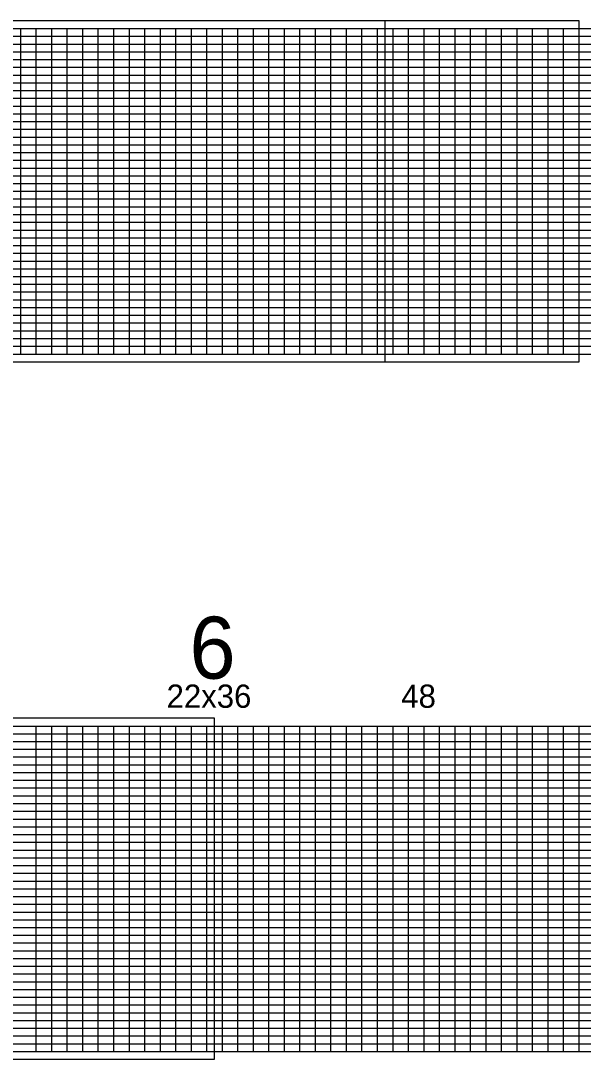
# Model space of a CAD drawing. Extents: x 1894907 to 1905782, y 740939 to 777025.
# Drawn here: x 1896732 to 1898545, y 765939 to 769289 of the extents above; entities that cross this region are included whole.
import ezdxf

# ---------------------------------------------------------------- set-up
doc = ezdxf.new("R2010")
doc.units = 0
for name, color, linetype in [('RD_PD_WallFill', 7, 'Continuous'), ('RD_SHT_IplotShp', 7, 'Continuous'), ('RD_Sketch8', 7, 'Continuous')]:
    doc.layers.add(name, color=color, linetype=linetype)

msp = doc.modelspace()

# ---------------------------------------------------------------- linework, layer by layer
at = {"layer": 'RD_PD_WallFill'}
for p, q in [((1894931.6, 769264.2), (1900281.6, 769264.2)), ((1896731.7, 768214.2), (1896731.6, 769264.2)), ((1896781.7, 768214.2), (1896781.6, 769264.2)), ((1896831.7, 768214.2), (1896831.6, 769264.2)), ((1896881.7, 768214.2), (1896881.6, 769264.2)), ((1896931.7, 768214.2), (1896931.6, 769264.2)), ((1896981.7, 768214.2), (1896981.6, 769264.2)), ((1897031.7, 768214.2), (1897031.6, 769264.2)), ((1897081.7, 768214.2), (1897081.6, 769264.2)), ((1897131.7, 768214.2), (1897131.6, 769264.2)), ((1897181.7, 768214.2), (1897181.6, 769264.2)), ((1897231.7, 768214.2), (1897231.6, 769264.2)), ((1897281.7, 768214.2), (1897281.6, 769264.2)), ((1897331.7, 768214.2), (1897331.6, 769264.2)), ((1897381.7, 768214.2), (1897381.6, 769264.2)), ((1897431.7, 768214.2), (1897431.6, 769264.2)), ((1897481.7, 768214.2), (1897481.6, 769264.2)), ((1897531.7, 768214.2), (1897531.6, 769264.2)), ((1897581.7, 768214.2), (1897581.6, 769264.2)), ((1897631.7, 768214.2), (1897631.6, 769264.2)), ((1897681.7, 768214.2), (1897681.6, 769264.2)), ((1897731.7, 768214.2), (1897731.6, 769264.2)), ((1897781.7, 768214.2), (1897781.6, 769264.2)), ((1897831.7, 768214.2), (1897831.6, 769264.2)), ((1897881.7, 768214.2), (1897881.7, 769264.2)), ((1897931.7, 768214.2), (1897931.7, 769264.2)), ((1897981.7, 768214.2), (1897981.7, 769264.2)), ((1898031.7, 768214.2), (1898031.7, 769264.2)), ((1898081.7, 768214.2), (1898081.7, 769264.2)), ((1898131.7, 768214.2), (1898131.7, 769264.2)), ((1898181.7, 768214.2), (1898181.7, 769264.2)), ((1898231.7, 768214.2), (1898231.7, 769264.2)), ((1898281.7, 768214.2), (1898281.7, 769264.2)), ((1898331.6, 768214.2), (1898331.7, 769264.2)), ((1898381.7, 768214.2), (1898381.7, 769264.2)), ((1898431.7, 768214.2), (1898431.7, 769264.2)), ((1898481.6, 768214.2), (1898481.7, 769264.2)), ((1898531.6, 768214.2), (1898531.7, 769264.2)), ((1895381.6, 769239.2), (1900281.6, 769239.2)), ((1895381.6, 769214.2), (1900281.6, 769214.2)), ((1895381.6, 769189.2), (1900281.6, 769189.2)), ((1895381.6, 769164.2), (1900281.6, 769164.2)), ((1895381.6, 769139.1), (1900281.6, 769139.2)), ((1894931.6, 769114.2), (1900281.6, 769114.2)), ((1894931.6, 769089.2), (1900281.6, 769089.1)), ((1894931.6, 769064.2), (1900281.6, 769064.2)), ((1894931.6, 769039.2), (1900281.6, 769039.1)), ((1894931.6, 769014.2), (1900281.6, 769014.2)), ((1894931.6, 768989.1), (1900281.6, 768989.2)), ((1894931.6, 768964.1), (1900281.6, 768964.2)), ((1894931.6, 768939.2), (1900281.6, 768939.1)), ((1894931.6, 768914.1), (1900281.6, 768914.2)), ((1894931.6, 768889.2), (1900281.6, 768889.2)), ((1894931.6, 768864.2), (1900281.6, 768864.1)), ((1894931.6, 768839.2), (1900281.6, 768839.2)), ((1894931.6, 768814.2), (1900281.6, 768814.1)), ((1894931.6, 768789.2), (1900281.6, 768789.2)), ((1894931.6, 768764.2), (1900281.6, 768764.2)), ((1894931.6, 768739.2), (1900281.6, 768739.1)), ((1894931.6, 768714.2), (1900281.6, 768714.2)), ((1894931.6, 768689.1), (1900281.6, 768689.2)), ((1894931.6, 768664.2), (1900281.6, 768664.2)), ((1894931.6, 768639.2), (1900281.6, 768639.2)), ((1894931.6, 768614.1), (1900281.6, 768614.2)), ((1894931.6, 768589.2), (1900281.6, 768589.1)), ((1894931.6, 768564.2), (1900281.6, 768564.2)), ((1894931.6, 768539.2), (1900281.6, 768539.2)), ((1894931.6, 768514.2), (1900281.6, 768514.1)), ((1894931.6, 768489.2), (1900281.6, 768489.2)), ((1894931.6, 768464.2), (1900281.6, 768464.2)), ((1894931.6, 768439.2), (1900281.6, 768439.2)), ((1894931.6, 768414.2), (1900281.6, 768414.2)), ((1894931.6, 768389.1), (1900281.6, 768389.2)), ((1894931.6, 768364.2), (1900281.6, 768364.1)), ((1894931.6, 768339.2), (1900281.6, 768339.2)), ((1894931.6, 768314.2), (1900281.6, 768314.2)), ((1894931.6, 768289.2), (1900281.6, 768289.2)), ((1894931.6, 768264.2), (1900281.6, 768264.2)), ((1894981.6, 768239.1), (1900281.6, 768239.2)), ((1894931.6, 768214.2), (1900281.6, 768214.1)), ((1895631.6, 767014.1), (1900981.6, 767014.1)), ((1895631.6, 767014.1), (1897381.6, 767014.1)), ((1895681.6, 767014.1), (1897381.6, 767014.1)), ((1896081.6, 766989.1), (1900981.6, 766989.1)), ((1896781.6, 765964.1), (1896781.6, 767014.1)), ((1896831.6, 765964.1), (1896831.6, 767014.1)), ((1896881.6, 765964.1), (1896881.6, 767014.1)), ((1896931.6, 765964.1), (1896931.6, 767014.1)), ((1896981.6, 765964.1), (1896981.6, 767014.1)), ((1897031.6, 765964.1), (1897031.6, 767014.1)), ((1897081.6, 765964.1), (1897081.6, 767014.1)), ((1897131.6, 765964.1), (1897131.6, 767014.1)), ((1897181.6, 765964.1), (1897181.6, 767014.1)), ((1897231.6, 765964.1), (1897231.6, 767014.1)), ((1897281.6, 765964.1), (1897281.6, 767014.1)), ((1897331.6, 765964.1), (1897331.6, 767014.1)), ((1897381.6, 765964.1), (1897381.6, 767014.1)), ((1897431.6, 765964.1), (1897431.6, 767014.1)), ((1897481.6, 765964.1), (1897481.6, 767014.1)), ((1897531.6, 765964.1), (1897531.6, 767014.1)), ((1897581.6, 765964.1), (1897581.6, 767014.1)), ((1897631.6, 765964.1), (1897631.6, 767014.1)), ((1897681.6, 765964.1), (1897681.6, 767014.1)), ((1897731.6, 765964.1), (1897731.6, 767014.1)), ((1897781.6, 765964.1), (1897781.6, 767014.1)), ((1897831.6, 765964.1), (1897831.6, 767014.1)), ((1897881.6, 765964.1), (1897881.6, 767014.1)), ((1897931.6, 765964.1), (1897931.6, 767014.1)), ((1897981.6, 765964.1), (1897981.6, 767014.1)), ((1898031.6, 765964.1), (1898031.6, 767014.1)), ((1898081.6, 765964.1), (1898081.6, 767014.1)), ((1898131.6, 765964.1), (1898131.6, 767014.1)), ((1898181.6, 765964.1), (1898181.6, 767014.1)), ((1898231.6, 765964.1), (1898231.6, 767014.1)), ((1898281.6, 765964.1), (1898281.6, 767014.1)), ((1898331.6, 765964.1), (1898331.6, 767014.1)), ((1898381.6, 765964.1), (1898381.6, 767014.1)), ((1898431.6, 765964.1), (1898431.6, 767014.1)), ((1898481.6, 765964.1), (1898481.6, 767014.1)), ((1898531.6, 765964.1), (1898531.6, 767014.1)), ((1896081.6, 766964.1), (1900981.6, 766964.1)), ((1896081.6, 766939.1), (1900981.6, 766939.1)), ((1896081.6, 766914.2), (1900981.6, 766914.1)), ((1896081.6, 766889.1), (1900981.6, 766889.2)), ((1895631.6, 766864.1), (1900981.6, 766864.1)), ((1895631.6, 766839.1), (1900981.6, 766839.1)), ((1895631.6, 766814.1), (1900981.6, 766814.2)), ((1895631.6, 766789.2), (1900981.6, 766789.1)), ((1895631.6, 766764.2), (1900981.6, 766764.2)), ((1895631.6, 766739.1), (1900981.6, 766739.1)), ((1895631.6, 766714.1), (1900981.6, 766714.1)), ((1895631.6, 766689.2), (1900981.6, 766689.1)), ((1895631.6, 766664.1), (1900981.6, 766664.1)), ((1895631.6, 766639.2), (1900981.6, 766639.1)), ((1895631.6, 766614.1), (1900981.6, 766614.1)), ((1895631.6, 766589.1), (1900981.6, 766589.2)), ((1895631.6, 766564.1), (1900981.6, 766564.1)), ((1895631.6, 766539.1), (1900981.6, 766539.2)), ((1895631.6, 766514.1), (1900981.6, 766514.1)), ((1895631.6, 766489.1), (1900981.6, 766489.1)), ((1895631.6, 766464.2), (1900981.6, 766464.1)), ((1895631.6, 766439.1), (1900981.6, 766439.1)), ((1895631.6, 766414.1), (1900981.6, 766414.1)), ((1895631.6, 766389.1), (1900981.6, 766389.1)), ((1895631.6, 766364.1), (1900981.6, 766364.2)), ((1895631.6, 766339.1), (1900981.6, 766339.1)), ((1895631.6, 766314.1), (1900981.6, 766314.1)), ((1895631.6, 766289.1), (1900981.6, 766289.1)), ((1895631.6, 766264.1), (1900981.6, 766264.1)), ((1895631.6, 766239.1), (1900981.6, 766239.1)), ((1895631.6, 766214.1), (1900981.6, 766214.1)), ((1895631.6, 766189.1), (1900981.6, 766189.1)), ((1895631.6, 766164.1), (1900981.6, 766164.1)), ((1895631.6, 766139.1), (1900981.6, 766139.1)), ((1895631.6, 766114.1), (1900981.6, 766114.1)), ((1895631.6, 766089.1), (1900981.6, 766089.1)), ((1895631.6, 766064.1), (1900981.6, 766064.1)), ((1895631.6, 766039.1), (1900981.6, 766039.1)), ((1895631.6, 766014.1), (1900981.6, 766014.1)), ((1895681.6, 765989.1), (1900981.6, 765989.1)), ((1895631.6, 765964.1), (1900981.6, 765964.1))]:
    msp.add_line(p, q, dxfattribs=at)
at = {"layer": 'RD_SHT_IplotShp'}
for points in [[(1894906.6, 768189.2), (1898531.7, 768189.2), (1898531.7, 769289.2), (1894906.6, 769289.2)], [(1894906.6, 768189.2), (1897905.8, 768189.2), (1897905.8, 769289.1), (1894906.6, 769289.1)], [(1895606.6, 765939.1), (1897356.6, 765939.1), (1897356.6, 767039.1), (1895606.6, 767039.1)]]:
    msp.add_lwpolyline(points, close=True, dxfattribs=at)

# ---------------------------------------------------------------- texts
at = {"layer": 'RD_PD_WallFill'}
for s, p in [('22x36', (1897201.7, 767072.8)), ('48', (1897958.3, 767072.8))]:
    msp.add_text(s, height=75, dxfattribs=at).set_placement(p)
at = {"layer": 'RD_Sketch8'}
msp.add_text('6', height=200, dxfattribs=at).set_placement((1897275.5, 767166.8))

doc.saveas('drawing.dxf')
